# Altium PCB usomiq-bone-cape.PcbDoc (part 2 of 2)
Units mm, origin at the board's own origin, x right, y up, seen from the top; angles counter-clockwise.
Board outline 86.36 x 54.61 mm, 2 copper layers (Top Layer, Bottom Layer); 72 components, 131 nets, 473 pads, 192 vias.
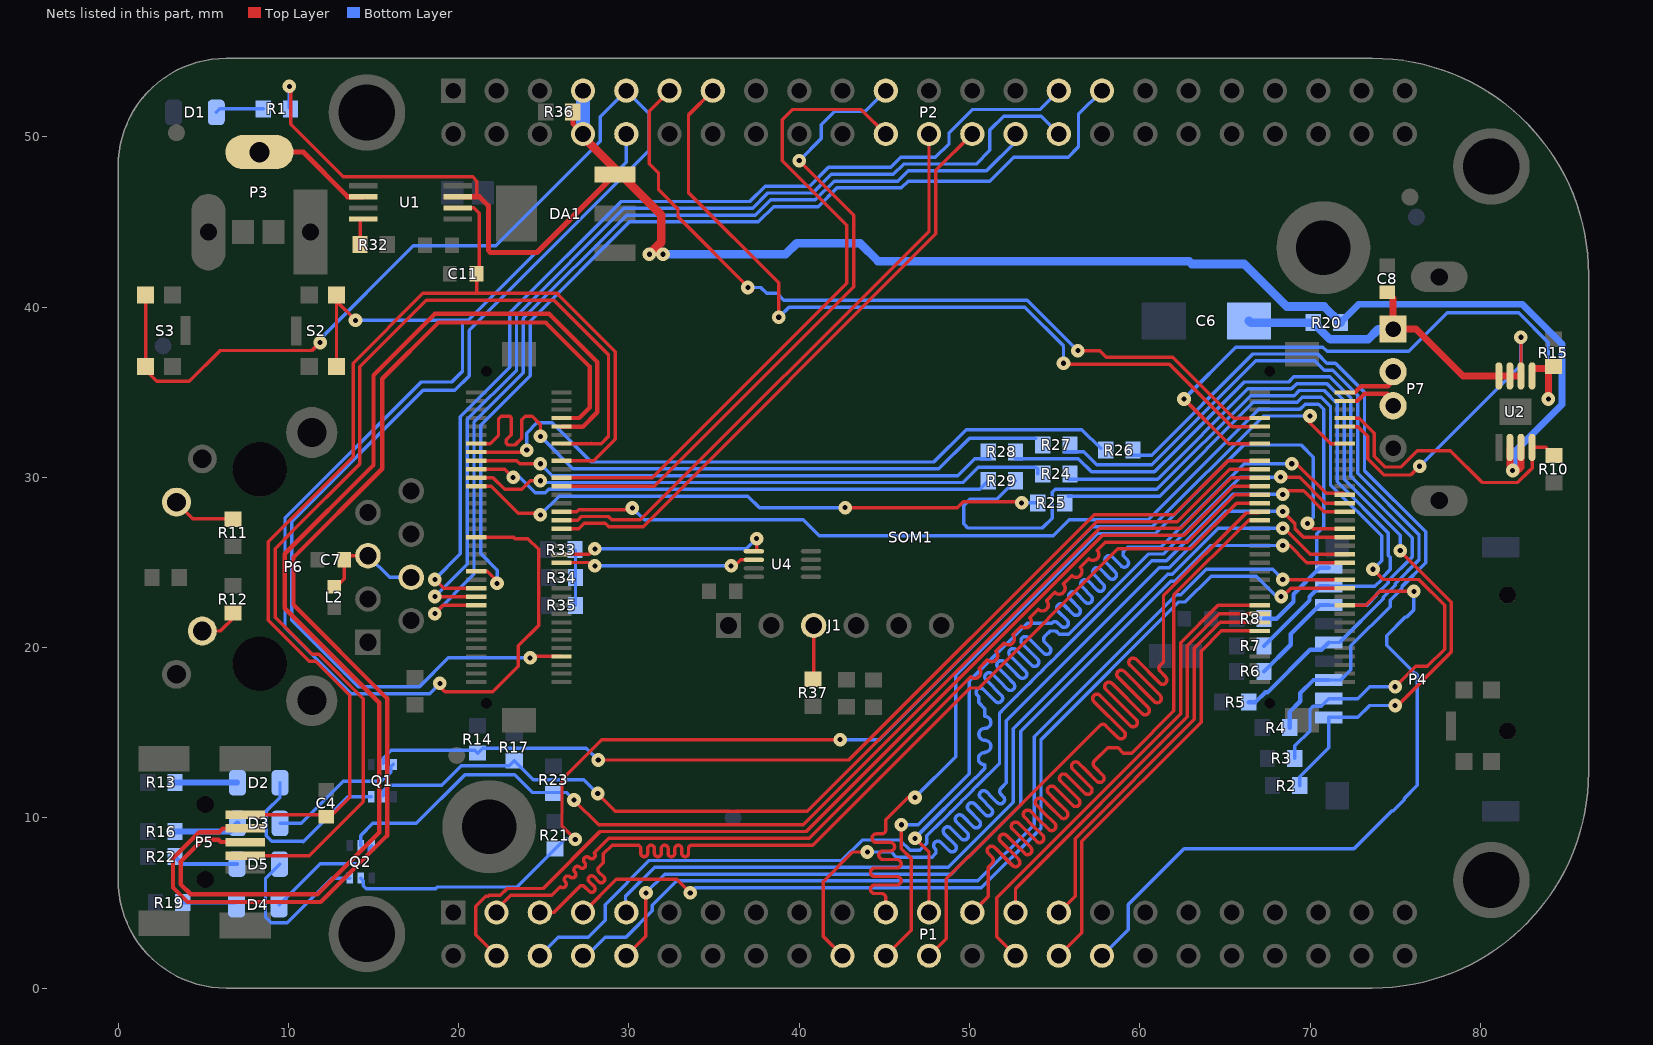
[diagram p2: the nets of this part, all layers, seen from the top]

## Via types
v1: diameter 0.8, hole 0.3, Top Layer to Bottom Layer, tented both sides, 187 vias
v2: diameter 0.4, hole 0.2, Top Layer to Bottom Layer, 5 vias

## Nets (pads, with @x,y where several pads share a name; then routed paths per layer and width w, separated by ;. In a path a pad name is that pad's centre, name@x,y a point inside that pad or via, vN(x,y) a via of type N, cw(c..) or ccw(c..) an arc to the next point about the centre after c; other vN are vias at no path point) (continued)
LCD_DATA15: P1.32 SOM1.B19 | length 40.8
  Top Layer w0.2: SOM1.B19@72.039,22.482 73.282,22.482 74.1,23.3 v1(76.1,23.3)
  Bottom Layer w0.2: P1.32@57.785,1.905 59.315,3.435 59.315,4.915 62.6,8.2 72.582,8.2 74.813,10.432 74.878,10.432 75.522,11.076 75.522,11.14 76.3,11.918 76.3,18.4 76.2,18.5 76.144,18.5 74.5,20.144 74.5,20.7 75.6,21.8 75.69,21.8 76.1,22.21 v1(76.1,23.3)
LCD_DE: P1.30 SOM1.B14 | length 25.3
  Top Layer w0.2: P1.30@55.245,1.905 56.6,3.26 56.6,8.617 63.6,15.617 63.6,19.79 64.792,20.982 SOM1.B14@67.039,20.982
LCD_HSYNC: P1.29 SOM1.B16 | length 23.3
  Top Layer w0.2: P1.29@55.245,4.445 56.2,5.4 56.2,8.783 63.2,15.783 63.2,19.956 64.726,21.482 SOM1.B16@67.039,21.482
LCD_PCLK: P1.28 SOM1.B20 | length 28.9
  Top Layer w0.2: P1.28@52.705,1.905 51.6,3.01 51.6,5.314 62.4,16.114 62.4,20.287 64.595,22.482 SOM1.B20@67.039,22.482
LCD_VSYNC: P1.27 SOM1.B18 | length 24.9
  Top Layer w0.2: P1.27@52.705,4.445 52.705,5.854 62.8,15.949 62.8,20.121 64.661,21.982 SOM1.B18@67.039,21.982
MMC0_CD: P4.9 R8.1 SOM1.A41 | length 63
  Top Layer w0.2: SOM1.A41@26.039,27.982 26.929,27.982 27.047,28.1 v1@29.864,28.1
  Bottom Layer w0.2: v1(30.2,28.2) 30.9,27.5 40.242,27.5 41.173,26.568 54.915,26.568 55.846,27.5 60.5,27.5 67,34 69.41,34 69.71,34.3 70.5,34.3 70.8,34 70.8,27.1 70.4,26.7 P4.9@70.4,24.9
  Bottom Layer w0.254: R8.1@67.3,21.7 68.028,21.7 69.027,22.699 69.027,23.139 70.588,24.7 P4.9@71.1,24.7
MMC0_CLKO: R27.2 SOM1.A58 | length 39.8
  Top Layer w0.2: SOM1.A58@21.039,31.982 21.866,31.982 22.339,32.455 22.339,33.421 22.5,33.582 23.018,33.582 23.1,33.5 23.1,32.5 22.8,32.2 22.8,32 22.9,31.9 23.31,31.9 23.7,32.29 23.7,33.382 23.9,33.582 24.31,33.582 24.807,33.085 v1(24.807,32.407)
  Bottom Layer w0.2: v1(24.807,32.407) 26.714,30.5 48.2,30.5 50,32.3 R27.2@53.9,32.3
MMC0_CMD: R26.2 SOM1.A56 | length 40.4
  Top Layer w0.2: SOM1.A56@21.039,31.482 23.882,31.482 v1(24,31.6) v1@24,31.8
  Bottom Layer w0.2: v1(24,31.6) 24,32.6 24.6,33.2 25.5,33.2 27.8,30.9 47.9,30.9 49.8,32.8 56.6,32.8 R26.2@57.7,31.7
MMC0_DAT0: R28.2 SOM1.A54 | length 30.9
  Top Layer w0.2: SOM1.A54@21.039,30.982 23.418,30.982 23.6,30.8 v1(24.8,30.8)
  Bottom Layer w0.2: v1(24.8,30.8) 25.5,30.1 49.3,30.1 50.3,31.1 51.1,31.1 R28.2@51.2,31.1
MMC0_DAT1: R29.2 SOM1.A52 | length 30.9
  Top Layer w0.2: SOM1.A52@21.039,30.482 22.718,30.482 v1(23.2,30)
  Bottom Layer w0.2: v1(23.2,30) 23.6,30 24.5,29.1 25.09,29.1 25.29,29.3 50.6,29.3 R29.2@51.1,29.8
MMC0_DAT2: R24.2 SOM1.A50 | length 34.2
  Top Layer w0.2: SOM1.A50@21.039,29.982 22.018,29.982 22.7,29.3 23.7,29.3 24.2,29.8 v1(24.8,29.8)
  Bottom Layer w0.2: v1(24.8,29.8) 24.9,29.7 49.626,29.7 50.526,30.6 53.9,30.6 54,30.5 R24.2@54,30.2
MMC0_DAT3: R25.2 SOM1.A48 | length 34.6
  Top Layer w0.2: SOM1.A48@21.039,29.482 21.918,29.482 23.5,27.9 24.7,27.9 v1(24.8,27.8) ; v1(42.697,28.219) 49.276,28.219 49.632,28.575 52.984,28.575 v1(53.061,28.499)
  Bottom Layer w0.2: v1(24.8,27.8) 25.9,28.9 36.988,28.9 37.668,28.219 v1(42.697,28.219) ; v1(53.061,28.499) 53.999,28.499 R25.2@54,28.5
MMC1_CLK: P1.21 SOM1.B37 | length 58.1
  Top Layer w0.2: P1.21@45.085,4.445 45.085,5.309 ccw(c44.835,5.309) 44.835,5.559 44.435,5.559 cw(c44.435,5.809) 44.185,5.809 cw(c44.435,5.809) 44.435,6.059 45.735,6.059 ccw(c45.735,6.309) 45.985,6.309 ccw(c45.735,6.309) 45.735,6.559 44.435,6.559 cw(c44.435,6.809) 44.185,6.809 cw(c44.435,6.809) 44.435,7.059 45.735,7.059 ccw(c45.735,7.309) 45.985,7.309 ccw(c45.735,7.309) 45.735,7.559 44.93,7.559 cw(c44.93,7.809) 44.68,7.809 cw(c44.93,7.809) 44.93,8.059 45.35,8.059 ccw(c45.35,8.309) 45.6,8.309 ccw(c45.35,8.309) 45.35,8.559 44.525,8.559 cw(c44.525,8.809) 44.275,8.809 cw(c44.525,8.809) 44.525,9.059 44.835,9.059 ccw(c44.835,9.309) 45.085,9.309 45.085,9.885 46.4,11.2 v1(46.8,11.2) ; v1(69.85,27.3) 70.168,26.982 SOM1.B37@72.039,26.982
  Bottom Layer w0.2: v1(46.8,11.2) 49.194,13.594 49.194,18.383 57.51,26.7 60.909,26.7 66.109,31.9 69.471,31.9 70.2,31.171 70.2,27.65 v1(69.85,27.3)
MMC1_CMD: P1.20 SOM1.B35 | length 58.9
  Top Layer w0.2: P1.20@42.545,1.905 41.415,3.035 41.415,6.261 43.154,8 v1(44,8) ; v1(68.4,28) 68.61,28 68.61,27.79 69.116,27.284 69.116,26.984 69.618,26.482 SOM1.B35@72.039,26.482
  Bottom Layer w0.2: v1(44,8) 45.4,8 45.7,7.7 47.807,7.7 47.961,7.855 ccw(c47.785,8.032) 47.961,8.208 ; 47.961,8.209 cw(c48.138,8.386) 47.961,8.562 cw(c48.138,8.386) 48.315,8.562 48.801,8.076 ccw(c48.978,8.253) 49.155,8.076 ccw(c48.978,8.253) 49.155,8.429 48.534,9.05 cw(c48.711,9.226) 48.534,9.403 cw(c48.711,9.226) 48.888,9.403 49.514,8.777 ccw(c49.691,8.954) 49.868,8.777 ccw(c49.691,8.954) 49.868,9.131 49.242,9.757 cw(c49.418,9.934) 49.242,10.11 cw(c49.418,9.934) 49.595,10.11 50.221,9.484 ccw(c50.398,9.661) 50.575,9.484 ccw(c50.398,9.661) 50.575,9.838 49.949,10.464 cw(c50.125,10.641) 49.949,10.817 cw(c50.125,10.641) 50.302,10.817 50.928,10.191 ccw(c51.105,10.368) 51.282,10.191 ccw(c51.105,10.368) 51.282,10.545 50.656,11.171 cw(c50.833,11.348) 50.656,11.524 cw(c50.833,11.348) 51.009,11.524 51.32,11.214 51.635,10.899 ccw(c51.812,11.075) 51.989,10.899 ccw(c51.812,11.075) 51.989,11.252 51.851,11.39 cw(c52.027,11.567) 51.851,11.744 52.165,12.059 52.165,15.711 61.154,24.7 61.737,24.7 65.037,28 v1(68.4,28)
MMC1_DAT0: P1.25 SOM1.B40 | length 60
  Top Layer w0.2: P1.25@50.165,4.445 51.105,5.385 51.105,7.112 51.332,7.34 ccw(c51.156,7.516) 51.332,7.693 51.115,7.911 cw(c51.291,8.088) 51.115,8.265 cw(c51.291,8.088) 51.468,8.265 52.527,7.205 ccw(c52.704,7.382) 52.881,7.205 ccw(c52.704,7.382) 52.881,7.559 51.822,8.618 cw(c51.999,8.795) 51.822,8.972 cw(c51.999,8.795) 52.175,8.972 53.235,7.912 ccw(c53.411,8.089) 53.588,7.912 ccw(c53.411,8.089) 53.588,8.266 52.529,9.325 cw(c52.706,9.502) 52.529,9.679 cw(c52.706,9.502) 52.882,9.679 53.942,8.619 ccw(c54.118,8.796) 54.295,8.619 ccw(c54.118,8.796) 54.295,8.973 53.631,9.638 53.236,10.032 cw(c53.413,10.209) 53.236,10.386 cw(c53.413,10.209) 53.589,10.386 53.984,9.991 54.649,9.327 ccw(c54.826,9.503) 55.002,9.327 ccw(c54.826,9.503) 55.002,9.68 54.338,10.345 53.943,10.739 cw(c54.12,10.916) 53.943,11.093 cw(c54.12,10.916) 54.297,11.093 54.691,10.698 55.356,10.034 ccw(c55.533,10.21) 55.709,10.034 ccw(c55.533,10.21) 55.709,10.387 55.045,11.052 54.65,11.447 cw(c54.827,11.623) 54.65,11.8 cw(c54.827,11.623) 55.004,11.8 55.398,11.405 56.063,10.741 ccw(c56.24,10.918) 56.417,10.741 ccw(c56.24,10.918) 56.417,11.094 55.752,11.759 55.357,12.154 cw(c55.534,12.33) 55.357,12.507 cw(c55.534,12.33) 55.711,12.507 56.105,12.113 56.77,11.448 ccw(c56.947,11.625) 57.124,11.448 ccw(c56.947,11.625) 57.124,11.801 56.459,12.466 56.064,12.861 cw(c56.241,13.038) 56.064,13.214 cw(c56.241,13.038) 56.418,13.214 56.812,12.82 57.477,12.155 ccw(c57.654,12.332) 57.831,12.155 ccw(c57.654,12.332) 57.831,12.509 57.343,12.996 cw(c57.52,13.173) 57.343,13.35 58.115,14.122 58.725,14.122 59.039,13.808 59.528,13.808 62,16.28 62,23.092 66.39,27.482 SOM1.B40@67.039,27.482
MMC1_DAT1: P1.24 SOM1.B42 | length 58.3
  Top Layer w0.2: P1.24@47.625,1.905 48.635,2.915 48.635,6.425 49.91,7.7 49.94,7.7 57.662,15.422 cw(c57.839,15.245) 58.016,15.422 58.723,14.715 ccw(c58.9,14.892) 59.077,14.715 ccw(c58.9,14.892) 59.077,15.069 57.309,16.836 cw(c57.486,17.013) 57.309,17.19 cw(c57.486,17.013) 57.662,17.19 59.43,15.422 ccw(c59.607,15.599) 59.784,15.422 ccw(c59.607,15.599) 59.784,15.776 58.016,17.544 cw(c58.193,17.72) 58.016,17.897 cw(c58.193,17.72) 58.37,17.897 60.137,16.129 ccw(c60.314,16.306) 60.491,16.129 ccw(c60.314,16.306) 60.491,16.483 58.723,18.251 cw(c58.9,18.427) 58.723,18.604 cw(c58.9,18.427) 59.077,18.604 60.844,16.836 ccw(c61.021,17.013) 61.198,16.836 ccw(c61.021,17.013) 61.198,17.19 59.43,18.958 cw(c59.607,19.135) 59.43,19.311 cw(c59.607,19.135) 59.784,19.311 61.173,17.922 ccw(c61.35,18.099) 61.527,17.922 ccw(c61.35,18.099) 61.527,18.275 61.198,18.604 cw(c61.375,18.781) 61.198,18.958 61.392,19.152 61.392,23.05 66.249,27.907 66.964,27.907 SOM1.B42@67.039,27.982
MMC1_DAT2: P1.5 SOM1.B44 | length 59.1
  Top Layer w0.2: P1.5@24.765,4.445 25.578,4.445 27.104,5.971 cw(c27.245,5.83) 27.386,5.971 27.67,5.688 ccw(c27.811,5.83) 27.952,5.688 ccw(c27.811,5.83) 27.952,5.971 27.67,6.254 ; 27.669,6.254 cw(c27.811,6.395) 27.67,6.537 cw(c27.811,6.395) 27.952,6.537 28.235,6.254 ; 28.235,6.254 ccw(c28.377,6.395) 28.518,6.254 ccw(c28.377,6.395) 28.518,6.537 28.235,6.82 cw(c28.377,6.961) 28.235,7.102 28.5,7.367 28.5,7.89 29.01,8.4 30.499,8.4 cw(c30.499,8.2) 30.699,8.2 30.699,7.922 ccw(c30.899,7.922) 30.899,7.722 ccw(c30.899,7.922) 31.099,7.922 31.099,8.2 cw(c31.299,8.2) 31.299,8.4 cw(c31.299,8.2) 31.499,8.2 31.499,7.922 ccw(c31.699,7.922) 31.699,7.722 ccw(c31.699,7.922) 31.899,7.922 31.899,8.2 cw(c32.099,8.2) 32.099,8.4 cw(c32.099,8.2) 32.299,8.2 32.299,7.922 ccw(c32.499,7.922) 32.499,7.722 ccw(c32.499,7.922) 32.699,7.922 32.699,8.2 cw(c32.899,8.2) 32.899,8.4 cw(c32.899,8.2) 33.099,8.2 33.099,7.922 ccw(c33.299,7.922) 33.299,7.722 ccw(c33.299,7.922) 33.499,7.922 33.499,8.2 cw(c33.699,8.2) 33.699,8.4 40.792,8.4 50.013,17.62 50.013,17.628 50.521,17.628 50.533,17.615 58.718,25.8 63,25.8 65.682,28.482 SOM1.B44@67.039,28.482
MMC1_DAT3: P1.6 SOM1.B41 | length 62.1
  Top Layer w0.2: v1@68.4,29.2 68.401,29.201 69.618,29.201 70.838,27.982 SOM1.B41@72.039,27.982
  Bottom Layer w0.2: P1.6@24.765,1.905 25.86,3 27.6,3 28.6,4 28.6,4.9 31.2,7.5 42.5,7.5 43.7,8.7 45.91,8.7 46.51,8.1 47.09,8.1 47.5,8.51 47.5,8.952 48.386,9.839 48.404,9.839 48.806,10.24 48.806,10.258 49.093,10.546 49.111,10.546 49.513,10.948 49.513,10.966 49.801,11.253 49.819,11.253 50.22,11.655 50.22,11.673 50.508,11.96 50.526,11.96 51.765,13.2 51.765,16.159 52.018,16.412 52.025,16.412 52.169,16.556 ; 52.165,16.559 52.169,16.556 ; 52.872,17.266 52.876,17.263 ; 53.579,17.973 53.583,17.97 ; 54.287,18.68 54.29,18.677 ; 54.994,19.387 54.997,19.384 ; v1(68.4,29) 65.472,29 61.572,25.1 60.706,25.1 55.141,19.535 55.141,19.528 54.997,19.384 ; 52.169,16.556 52.312,16.699 52.312,16.706 52.725,17.119 52.732,17.119 52.876,17.263 ; 52.876,17.263 53.019,17.406 53.019,17.414 53.432,17.826 53.439,17.826 53.583,17.97 ; 53.583,17.97 53.727,18.113 53.727,18.121 54.139,18.533 54.146,18.533 54.29,18.677 ; 54.29,18.677 54.434,18.821 54.434,18.828 54.846,19.24 54.853,19.24 54.997,19.384
MMC1_DAT4: P1.23 SOM1.B43 | length 58.5
  Top Layer w0.2: v1(46.8,8.8) 47.625,7.975 P1.23@47.625,4.445 ; v1@68.4,30 69.385,30 70.903,28.482 SOM1.B43@72.039,28.482
  Bottom Layer w0.2: v1(46.8,8.8) 46.8,8.818 50.342,12.36 50.36,12.36 50.902,12.902 50.902,13.129 ; 50.876,13.129 cw(c50.876,13.479) 50.876,13.829 ; 50.902,13.857 ccw(c50.902,14.207) 50.902,14.557 cw(c50.902,14.907) 50.902,15.257 ccw(c50.902,15.607) 50.902,15.957 50.902,16.408 50.533,16.777 50.533,17.13 50.467,17.197 cw(c50.644,17.374) 50.467,17.55 cw(c50.644,17.374) 50.82,17.55 51.523,16.847 ccw(c51.7,17.024) 51.877,16.847 ccw(c51.7,17.024) 51.877,17.201 50.975,18.103 cw(c51.152,18.279) 50.975,18.456 cw(c51.152,18.279) 51.329,18.456 51.771,18.014 52.23,17.555 ccw(c52.407,17.731) 52.584,17.555 ccw(c52.407,17.731) 52.584,17.908 52.124,18.368 51.682,18.81 cw(c51.859,18.987) 51.682,19.163 cw(c51.859,18.987) 52.036,19.163 52.478,18.721 52.937,18.262 ccw(c53.114,18.438) 53.291,18.262 ccw(c53.114,18.438) 53.291,18.615 52.831,19.075 52.389,19.517 cw(c52.566,19.694) 52.389,19.87 cw(c52.566,19.694) 52.743,19.87 53.185,19.428 53.645,18.969 ccw(c53.821,19.146) 53.998,18.969 ccw(c53.821,19.146) 53.998,19.322 53.538,19.782 53.096,20.224 cw(c53.273,20.401) 53.096,20.578 cw(c53.273,20.401) 53.45,20.578 53.892,20.135 54.352,19.676 ccw(c54.528,19.853) 54.705,19.676 ccw(c54.528,19.853) 54.705,20.029 54.422,20.312 cw(c54.599,20.489) 54.422,20.666 54.733,20.976 55.081,20.976 55.283,20.774 55.761,20.774 55.783,20.796 55.836,20.796 60.54,25.5 61.406,25.5 65.906,30 v1@68.275,30
  other v1: 68.275,30.025
MMC1_DAT5: P1.22 SOM1.B45 | length 58.7
  Top Layer w0.2: P1.22@45.085,1.905 46.584,3.404 46.584,7.616 46,8.2 v1(46,9.6) ; v1@69.261,30.861 69.261,30.8 69.261,30.752 70.955,29.057 71.964,29.057 SOM1.B45@72.039,28.982
  Bottom Layer w0.2: v1(46,9.6) 47,9.6 49.994,12.594 49.994,18.04 53.396,21.443 54.844,21.443 cw(c55.021,21.266) 55.198,21.443 55.381,21.26 ccw(c55.558,21.437) 55.734,21.26 ccw(c55.558,21.437) 55.734,21.613 55.199,22.149 cw(c55.376,22.326) 55.199,22.502 cw(c55.376,22.326) 55.553,22.502 56.088,21.967 ccw(c56.265,22.144) 56.442,21.967 ccw(c56.265,22.144) 56.442,22.321 55.906,22.856 cw(c56.083,23.033) 55.906,23.21 cw(c56.083,23.033) 56.26,23.21 56.795,22.674 ccw(c56.972,22.851) 57.149,22.674 ccw(c56.972,22.851) 57.149,23.028 56.613,23.563 cw(c56.79,23.74) 56.613,23.917 cw(c56.79,23.74) 56.967,23.917 57.502,23.381 ccw(c57.679,23.558) 57.856,23.381 ccw(c57.679,23.558) 57.856,23.735 57.32,24.27 cw(c57.497,24.447) 57.32,24.624 cw(c57.497,24.447) 57.674,24.624 58.209,24.088 ccw(c58.386,24.265) 58.563,24.088 ccw(c58.386,24.265) 58.563,24.442 58.027,24.977 cw(c58.204,25.154) 58.027,25.331 cw(c58.204,25.154) 58.381,25.331 58.916,24.795 ccw(c59.093,24.972) 59.27,24.795 ccw(c59.093,24.972) 59.27,25.149 59.087,25.332 cw(c59.264,25.509) 59.087,25.686 59.301,25.9 61.24,25.9 66.14,30.8 v1(68.925,30.8) v1@69,30.8
MMC1_DAT6: P1.3 SOM1.B46 | length 60
  Top Layer w0.2: P1.3@22,4.4 22.135,4.535 23.055,5.455 25.47,5.455 25.979,5.964 ccw(c26.121,6.106) 26.262,6.247 cw(c26.404,6.388) 26.545,6.53 ccw(c26.686,6.671) 26.828,6.813 cw(c26.969,6.954) 27.111,7.096 ccw(c27.252,7.237) 27.394,7.378 cw(c27.535,7.52) 27.676,7.661 ccw(c27.818,7.803) 27.959,7.944 28.815,8.8 40.579,8.8 50.07,18.291 ccw(c50.312,18.544) 50.565,18.786 51.06,19.281 ccw(c51.307,19.529) 51.555,19.776 52.05,20.271 ccw(c52.297,20.519) 52.545,20.766 53.04,21.261 ccw(c53.287,21.509) 53.535,21.756 54.03,22.251 ccw(c54.277,22.499) 54.525,22.746 55.02,23.241 ccw(c55.267,23.488) 55.515,23.736 56.01,24.231 ccw(c56.257,24.478) 56.505,24.726 57,25.221 ccw(c57.247,25.468) 57.495,25.716 57.979,26.2 62.8,26.2 65.582,28.982 SOM1.B46@67.039,28.982
MMC1_DAT7: P1.4 SOM1.B48 | length 59.7
  Top Layer w0.2: P1.4@22.225,1.905 21,3.13 21,4.8 21.6,5.4 21.752,5.4 21.807,5.455 22.455,5.455 22.855,5.855 24.956,5.855 28.301,9.2 40.413,9.2 57.813,26.6 62.6,26.6 65.482,29.482 SOM1.B48@67.039,29.482
NetC7_1: C7.1 L2.2 P6.4 P6.5 | length 6.3
  Top Layer w0.2: L2.2@12.862,23.612 13.284,24.034 C7.1@13.284,25.171 13.508,25.395 P6.5@14.675,25.395
  Bottom Layer w0.2: P6.5@14.675,25.395 15.945,24.125 P6.4@17.215,24.125
NetD1_1: D1.1 R1.1 | length 2.8
  Bottom Layer w0.2: D1.1@5.766,51.435 5.969,51.638 R1.1@8.522,51.638
NetD2_1: D2.1 R13.1 | length 3.6
  Bottom Layer w0.35: R13.1@3.34,12.09 D2.1@6.985,12.09
NetD2_2: D2.2 Q1.6 | length 10.8
  Bottom Layer w0.2: D2.2@9.51,12.065 9.51,11.205 8.71,10.405 8.71,8.95 9.033,8.627 10.854,8.627 10.871,8.611 13.503,11.242 Q1.6@14.869,11.242
NetD3_1: D3.1 R16.1 | length 3.9
  Bottom Layer w0.35: R16.1@3.34,9.195 6.528,9.195 D3.1@7.01,9.677
NetD3_2: D3.2 Q1.3 | length 8.3
  Bottom Layer w0.2: D3.2@9.51,9.677 10.77,9.677 13.233,12.141 15.468,12.141 16.019,12.693 16.019,12.992 Q1.3@16.169,13.142
NetD4_1: D4.1 R19.1 | length 3
  Bottom Layer w0.254: R19.1@3.797,5.029 D4.1@6.833,5.029
NetD4_2: D4.2 Q2.6 | length 7.1
  Bottom Layer w0.2: D4.2@9.46,4.902 11.873,7.315 14.147,7.315 14.749,7.918 14.749,8.217 Q2.6@14.899,8.367
NetD5_1: D5.1 R22.1 | length 3.8
  Bottom Layer w0.254: R22.1@3.34,7.722 3.772,7.29 D5.1@6.985,7.29
NetD5_2: D5.2 Q2.3 | length 9.6
  Bottom Layer w0.2: D5.2@9.485,7.29 8.66,6.464 8.66,4.174 8.982,3.852 9.937,3.852 12.552,6.467 Q2.3@13.599,6.467
NetJ1_3: J1.3 R37.1 | length 3.1
  Top Layer w0.2: R37.1@40.85,18.18 J1.3@40.85,21.3
NetP6_10: P6.10 R12.2 | length 2.3
  Top Layer w0.2: P6.10@4.945,20.975 6,20.975 R12.2@6.875,21.85
NetP6_11: P6.11 R11.2 | length 3.7
  Top Layer w0.2: P6.11@3.425,28.545 4.395,27.575 R11.2@6.756,27.575
NetR32_1: R32.1 U1.4 | length 1.3
  Top Layer w0.2: R32.1@14.211,43.663 14.211,44.993
NetR33_2: R33.2 R34.2 R35.2 | length 3.3
  Bottom Layer w0.2: R35.2@26.86,22.479 R34.2@26.86,24.105 R33.2@26.86,25.73
PWR_BUT: P2.9 S3.2 S3.4 SOM1.A7 | length 100.4
  Top Layer w0.2: S3.2@1.626,40.488 1.626,36.288 2.277,35.636 4.191,35.636 6.005,37.45 11.389,37.45 v1(11.862,37.922) ; v1(24.2,19.4) 24.282,19.482 SOM1.A7@26.039,19.482
  Bottom Layer w0.2: v1(11.862,37.922) 11.862,38.125 17.336,43.599 22.175,43.599 28.315,49.739 28.315,51.175 P2.9@29.845,52.705 31.19,51.36 ; v1(24.2,19.4) 19.4,19.4 17.7,17.7 14.1,17.7 10.2,21.6 10.2,27.4 17.906,35.106 19.78,35.106 20.626,35.952 20.626,38.627 31.2,49.2 31.2,51.36
SD_CLK: P4.5 R5.1 R27.1 | length 45.6
  Bottom Layer w0.2: R27.1@55.6,31.5 55.9,31.5 56.7,31.5 57.467,30.733 60.699,30.733 66.81,36.845 70.284,36.845 70.828,36.3 71.328,36.3 72.8,34.828 72.8,30.228 76.4,26.628 76.4,25.156 75,23.756 75,23.655 74.944,23.6 74.3,22.956 74.3,22.868 71.731,20.3 P4.5@71.1,20.3
  Bottom Layer w0.254: R5.1@66.4,16.8 66.803,16.8 67.374,17.372 67.5,17.372 70.005,19.877 70.677,19.877 P4.5@71.1,20.3
SD_CMD: P4.3 R4.1 R26.1 | length 42.5
  Bottom Layer w0.2: R26.1@59.5,31.3 59.6,31.3 60.7,31.3 66.644,37.245 70.45,37.245 70.994,36.7 71.494,36.7 73.2,34.994 73.2,30.4 76.8,26.8 76.8,24.99 75.4,23.59 75.4,23.49 75.11,23.2 74.7,22.79 74.7,22.4 72.4,20.1 72.4,18.7 71.8,18.1 P4.3@71.1,18.1
  Bottom Layer w0.254: R4.1@68.8,15.3 68.8,16.222 69.427,16.849 69.427,17.327 70.2,18.1 P4.3@71.1,18.1
SD_D0: P4.7 R6.1 R28.1 | length 45.6
  Bottom Layer w0.2: R28.1@52.7,31.1 56.4,31.1 57.167,30.333 60.865,30.333 66.131,35.6 68.747,35.6 69.047,35.9 71.163,35.9 72.4,34.663 72.4,30.063 76,26.463 76,25.321 74.6,23.921 74.6,23.821 73.9,23.121 73.9,23.034 73.366,22.5 P4.7@71.1,22.5
  Bottom Layer w0.254: R6.1@67.3,18.6 68.873,20.173 68.873,20.801 70.572,22.5 P4.7@71.1,22.5
SD_D1: P4.8 R7.1 R29.1 | length 51.8
  Bottom Layer w0.2: R29.1@52.7,29.8 51.602,28.702 50.013,28.702 49.657,28.346 49.657,27.28 49.911,27.026 54.28,27.026 54.85,27.596 54.85,29.124 55.026,29.3 61.01,29.3 66.51,34.8 69.079,34.8 69.379,35.1 70.831,35.1 71.6,34.331 71.6,29.731 74.6,26.731 74.6,25.41 74.7,25.31 74.7,24.587 74.2,24.087 74.2,23.987 73.813,23.6 P4.8@71.1,23.6
  Bottom Layer w0.254: R7.1@67.3,20.1 69.973,22.773 69.973,22.985 70.588,23.6 P4.8@71.1,23.6
SD_D2: P4.1 R2.1 R24.1 | length 49.8
  Top Layer w0.2: v1(75,16.6) 75.156,16.6 78.3,19.744 78.3,22.656 75.3,25.655 v1(75.3,25.7)
  Bottom Layer w0.2: R24.1@55.8,29.9 55.9,29.9 61.044,29.9 66.344,35.2 68.913,35.2 69.213,35.5 70.997,35.5 72,34.497 72,29.897 75.3,26.597 v1(75.3,25.7) ; R2.1@69.4,11.9 69.4,12.426 71.1,14.126 P4.1@71.1,15.9 72.8,15.9 73.5,16.6 v1(75,16.6)
SD_D3: P4.2 R3.1 R25.1 | length 49.3
  Top Layer w0.2: v1(73.7,24.6) 74.3,24 76.39,24 77.9,22.49 77.9,19.91 76.89,18.9 76.2,18.9 v1(75,17.7)
  Bottom Layer w0.2: R25.1@55.8,28.9 61.175,28.9 66.675,34.4 69.244,34.4 69.544,34.7 70.666,34.7 71.2,34.166 71.2,29.566 74.2,26.566 74.2,25.1 v1(73.7,24.6) ; R3.1@69.1,13.5 69.1,14.226 70,15.126 70,16.374 70.176,16.55 70.65,16.55 P4.2@71.1,17 72.8,17 73.5,17.7 v1(75,17.7)
SPI1_CS0: P2.28 SOM1.A20 | length 55.3
  Top Layer w0.2: v1(18.6,22) 19.082,22.482 SOM1.A20@21.039,22.482
  Bottom Layer w0.2: v1(18.6,22) 20.9,24.3 20.9,33.235 23.8,36.135 23.8,39.331 29.869,45.4 37.43,45.4 38.33,46.3 40.953,46.3 42.053,47.4 45.8,47.4 46.4,48 51,48 P2.28@52.705,49.705
SPI1_D0: P2.29 SOM1.A24 | length 58.2
  Top Layer w0.2: v1(18.6,24) 19.118,23.482 SOM1.A24@21.039,23.482
  Bottom Layer w0.2: v1(18.6,24) 20.1,25.5 20.1,33.566 23,36.466 23,39.663 29.537,46.2 37.099,46.2 37.999,47.1 40.621,47.1 41.721,48.2 45.366,48.2 45.966,48.8 48,48.8 48.8,49.6 48.8,50.228 50.172,51.6 54.14,51.6 P2.29@55.245,52.705
SPI1_D1: P2.30 SOM1.A22 | length 58.8
  Top Layer w0.2: v1(18.6,23) 18.618,22.982 SOM1.A22@21.039,22.982
  Bottom Layer w0.2: v1(18.6,23) 20.5,24.9 20.5,33.4 23.4,36.3 23.4,39.497 29.703,45.8 37.264,45.8 38.164,46.7 40.787,46.7 41.887,47.8 45.531,47.8 46.131,48.4 50.4,48.4 51.2,49.2 51.2,50.4 52,51.2 54.21,51.2 P2.30@55.245,50.165
SPI1_SCLK: P2.31 SOM1.A28 | length 58.6
  Top Layer w0.2: SOM1.A28@21.387,24.486 21.685,24.486 22.25,23.92 v1(22.25,23.774)
  Bottom Layer w0.2: v1(22.25,23.774) 22.276,23.8 22.276,24.551 21.3,25.527 21.3,33.069 24.2,35.969 24.2,39.166 30.034,45 37.596,45 38.496,45.9 41.118,45.9 42.218,47 46,47 46.4,47.4 51.2,47.4 52.6,48.8 55.8,48.8 56.4,49.4 56.4,51.32 P2.31@57.785,52.705
SYS_5V: DA1.3 P2.7 P2.8 R1.2 R20.2 R36.2 U1.7 U2.2 U2.3 | length 112.3
  Top Layer w0.2: v1(10.058,52.959) 10.135,52.883 10.135,50.749 13.233,47.65 20.821,47.65 21.07,47.401 21.07,46.621 21.214,46.477
  Top Layer w0.3: U1.7@19.945,46.477 21.214,46.477 21.742,45.949 21.742,43.332 21.869,43.205 24.603,43.205 DA1.3@29.189,47.791 ; R36.2@26.708,51.46 26.708,50.762 P2.8@27.305,50.165
  Top Layer w0.4: U2.2@81.739,31.757 81.739,30.661 82.1,30.3 82.389,30.589 U2.3@82.389,31.757
  Top Layer w0.508: P2.8@27.305,49.995 31.9,45.4 31.9,43.8 v1(31.2,43.1)
  Bottom Layer w0.2: R1.2@10.058,51.702 v1(10.058,52.959)
  Bottom Layer w0.4: R20.2@71.789,39.082 72.877,40.17 82.457,40.17 84.8,37.827 84.8,34.269 82.1,31.569 v1@82.1,30.3
  Bottom Layer w0.508: v1(32,43.1) 39.2,43.1 39.854,43.754 43.57,43.754 44.624,42.7 62.896,42.7 63.068,42.528 66.133,42.528 68.625,40.036 70.827,40.036 71.781,39.082 R20.2@71.789,39.082
  Bottom Layer w0.8: P2.8@27.305,50.165 P2.7@27.305,52.705
  other v1: 81.9,30.4
SYS_RESETN: P2.10 S2.2 S2.4 SOM1.A36 | length 78
  Top Layer w0.2: S2.2@12.827,36.5 12.827,40.335 v1(13.945,39.218) ; v1(18.9,17.9) 18.9,17.7 19.2,17.4 22,17.4 23.5,18.9 23.5,20.1 24.7,21.3 24.7,25.77 24.07,26.4 23.31,26.4 23.228,26.482 SOM1.A36@21.039,26.482
  Bottom Layer w0.2: v1(13.945,39.218) 13.954,39.227 20.227,39.227 ; v1(18.9,17.9) 18.3,17.3 13.7,17.3 9.8,21.2 9.8,27.6 17.8,35.6 19.59,35.6 20.227,36.237 20.227,39.227 ; P2.10@29.845,50.165 29.845,48.514 20.558,39.227 20.227,39.227
TIMER4: P1.7 SOM1.B23 | length 58
  Top Layer w0.2: P1.7@27.305,4.445 29.26,6.4 32.8,6.4 v1(33.6,5.6) ; v1@68.239,22.839 68.35,22.95 68.882,23.482 SOM1.B23@72.039,23.482
  Bottom Layer w0.2: v1(33.6,5.6) 33.9,5.9 50.7,5.9 54.2,9.4 54.2,14.593 62.289,22.682 62.682,22.682 64.2,24.2 66.839,24.2 68.169,22.87 68.239,22.8 68.3,22.861 v1(68.3,23) v1@68.3,23.293
TIMER5: P1.9 SOM1.B31 | length 55.3
  Top Layer w0.2: v1@68.575,26.925 70.018,25.482 SOM1.B31@72.039,25.482
  Bottom Layer w0.2: P1.9@29.8,4.2 29.8,4.445 29.8,5.39 31.51,7.1 48.756,7.1 49.1,7.444 49.1,7.456 49.744,8.1 49.756,8.1 52.576,10.92 52.576,15.232 61.644,24.3 61.903,24.3 64.603,27 v1(68.4,27)
TIMER6: P1.10 SOM1.B29 | length 56.6
  Top Layer w0.2: P1.10@29.845,1.905 31,3.06 v1(31,5.6) ; v1(68.4,26) 68.8,26 69.818,24.982 SOM1.B29@72.039,24.982
  Bottom Layer w0.2: v1(31,5.6) 32.1,6.7 48.922,6.7 49.5,7.278 49.5,7.29 49.91,7.7 49.922,7.7 53,10.778 53,15.09 61.81,23.9 62.069,23.9 64.169,26 v1(68.4,26)
TIMER7: P1.8 SOM1.B25 | length 57.3
  Top Layer w0.2: v1(68.4,24) 68.418,23.982 SOM1.B25@72.039,23.982
  Bottom Layer w0.2: P1.8@27.6,2 28.6,3 29.828,3 31.375,4.547 31.375,4.863 32.812,6.3 50.49,6.3 53.8,9.61 53.8,14.759 62.141,23.1 62.4,23.1 63.9,24.6 67.8,24.6 v1(68.4,24)
UART0_RX: SOM1.A29 U4.6 | length 11.6
  Top Layer w0.2: SOM1.A29@26.2,25 27.8,25 v1(28,24.8) ; v1(36,24.8) 36.2,24.8 36.557,25.157 U4.6@37.339,25.157
  Bottom Layer w0.2: v1@28.194,24.606 v1(28,24.8) v1(36,24.8)
UART0_TX: SOM1.A31 U4.5 | length 12.5
  Top Layer w0.2: SOM1.A31@26.039,25.482 27.682,25.482 v1(28,25.8) ; U4.5@37.5,25.7 v1(37.5,26.4)
  Bottom Layer w0.2: v1(28,25.8) 36.9,25.8 v1(37.5,26.4)
UART1_RXD: P2.26 SOM1.A37 | length 36.1
  Top Layer w0.2: SOM1.A37@26.039,26.982 27.061,26.982 27.379,27.3 28.621,27.3 28.821,27.1 30.831,27.1 48.025,44.294 48.025,48.025 P2.26@50.165,50.165
UART1_TXD: P2.24 SOM1.A39 | length 34.5
  Top Layer w0.2: SOM1.A39@26.039,27.482 26.995,27.482 27.213,27.7 28.787,27.7 28.987,27.5 30.666,27.5 47.625,44.459 P2.24@47.625,50.165
UART2_RXD: P2.22 SOM1.A49 | length 39.6
  Top Layer w0.2: SOM1.A49@26.039,29.982 31.382,29.982 42.8,41.4 42.8,44.8 39,48.6 39,49.742 38.995,49.747 38.995,50.995 39.6,51.6 43.65,51.6 P2.22@45.085,50.165
UART2_TXD: P2.21 SOM1.A47 | length 37.6
  Top Layer w0.2: SOM1.A47@26.039,29.482 31.482,29.482 43.2,41.2 43.2,45.4 40.3,48.3
  Bottom Layer w0.2: v1(40,48.6) 41.3,49.9 41.3,50.7 42.1,51.5 43.88,51.5 P2.21@45.085,52.705
UART4_RXD: P2.11 SOM1.B64 | length 48
  Top Layer w0.2: P2.11@32.385,52.705 31.191,51.511 31.191,48.412 31.739,47.864 31.739,46.9 32.881,45.758 32.881,45.3 37.008,41.173 v1@37.231,40.95 ; v1(56.363,37.44) 57.66,37.44 58.041,37.059 61.941,37.059 65.518,33.482 SOM1.B64@67.039,33.482
  Bottom Layer w0.2: v1(36.982,41.148) 37.752,41.148 38.1,40.8 38.7,40.8 39.1,40.4 53.402,40.4 v1(56.363,37.44)
UART4_TXD: P2.13 SOM1.B62 | length 48
  Top Layer w0.2: P2.13@34.925,52.705 33.5,51.28 33.5,46.72 38.8,41.42 v1(38.8,39.4) ; v1@55.606,36.652 61.748,36.652 65.418,32.982 SOM1.B62@67.039,32.982
  Bottom Layer w0.2: v1(38.8,39.4) 39.4,40 53.237,40 55.524,37.712 v1(55.524,36.703)
USB0_D_N: P5.2 SOM1.A63 | length 71.4
  Top Layer w0.254: P5.2@7.469,9.381 6.155,9.381 5.94,9.166 4.765,9.166 3.229,7.63 3.229,5.908 4.079,5.058 11.897,5.058 15.8,8.96 15.8,17.018 10.3,22.518 10.3,25.3 15.508,30.508 15.508,35.79 18.81,39.092 25.108,39.092 27.692,36.508 27.692,34.092 27.082,33.482 SOM1.A63@26.039,33.482
USB0_D_P: P5.3 SOM1.A61 | length 71.6
  Top Layer w0.254: P5.3@7.469,8.581 6.024,8.581 5.893,8.712 4.953,8.712 3.683,7.442 3.683,6.096 4.267,5.512 11.709,5.512 15.342,9.144 15.342,16.758 9.792,22.308 9.792,25.51 15,30.718 15,36 18.6,39.6 25.318,39.6 28.146,36.772 28.146,33.822 27.298,32.974 SOM1.A61@26.039,32.974
USB0_ID: P5.4 SOM1.A57 | length 64.1
  Top Layer w0.2: P5.4@7.469,7.781 11.22,7.781 14.4,10.961 14.4,17 11.8,19.6 11.4,19.6 9.225,21.775 9.225,25.81 10.207,26.792 ; 9.807,26.393 10.207,26.792 ; SOM1.A57@26.039,31.982 27.782,31.982 ; 27.8,32 27.782,31.982 ; 10.207,26.792 14.2,30.785 14.2,36.5 18.1,40.4 25.6,40.4 28.8,37.2 28.8,32.41 28.372,31.982 27.782,31.982
USB0_VBUS: C4.1 C11.2 P5.1 SOM1.A53 U1.6 | length 70
  Top Layer w0.2: P5.1@7.469,10.181 12.106,10.181 C4.1@12.219,10.068 12.468,10.068 13.6,11.2 13.6,17.206 11.606,19.2 11.234,19.2 8.825,21.609 8.825,26.225 9.561,26.961 13.8,31.2 13.8,36.7 17.9,40.8 21.057,40.8 ; U1.6@19.945,45.827 20.899,45.827 21.209,45.517 21.209,42.113 C11.2@21.057,41.961 21.057,40.8 ; 25.849,40.786 25.849,40.716 ; SOM1.A53@26.039,30.982 27.938,30.982 29.2,32.244 29.2,37.366 25.849,40.716 ; 21.057,40.8 25.766,40.8 25.849,40.716
USB1_DRVVBUS: R10.2 SOM1.B63 U2.4 | length 17.2
  Top Layer w0.2: SOM1.B63@72.039,33.482 72.884,33.482 73.779,32.587 73.779,31.249 74.423,30.605 75.335,30.605 76.29,31.56 78.24,31.56 80.1,29.7 82.207,29.7 82.889,30.382 82.889,30.389 83.039,30.539 U2.4@83.039,31.757 83.839,31.757 R10.2@84.314,31.282
USB1_N: P7.2 SOM1.B69 | length 3.7
  Top Layer w0.254: SOM1.B69@72.039,34.982 72.629,34.982 73.004,35.357 74.6,35.357 74.879,35.636 P7.2@74.879,36.205
USB1_OCN: R15.1 SOM1.B58 U2.5 | length 35.9
  Top Layer w0.2: v1(62.6,34.6) 65.218,31.982 SOM1.B58@67.039,31.982
  Top Layer w0.4: U2.5@83.1,36.4 R15.1@84.289,36.4 ; v1(84,34.6) 84,36.018
  Bottom Layer w0.2: v1(62.6,34.6) 65.644,37.644 70.755,37.644 71,37.4 75.8,37.4 78.07,39.67 82.25,39.67 84,37.92 v1(84,34.6)
USB1_P: P7.3 SOM1.B67 | length 3.5
  Top Layer w0.254: SOM1.B67@72.039,34.482 72.771,34.482 73.192,34.903 74.546,34.903 74.879,34.57 P7.3@74.879,34.205
USB1_VBUS: C6.1 C8.2 P7.1 R20.1 SOM1.B61 U2.6 U2.7 U2.8 | length 39
  Top Layer w0.2: SOM1.B61@72.039,32.982 72.818,32.982 73.379,32.421 73.379,31.084 74.323,30.14 75.93,30.14 v1(76.44,30.65) ; v1(82.38,38.23) 82.389,38.221 U2.6@82.389,35.957
  Top Layer w0.4: C8.2@74.539,40.87 74.879,40.53 P7.1@74.879,38.705 76.23,38.705 78.978,35.957 U2.8@81.089,35.957 U2.7@81.739,35.957 U2.6@82.389,35.957
  Bottom Layer w0.2: v1(76.44,30.65) 82.38,36.59 v1(82.38,38.23)
  Bottom Layer w0.508: C6.1@66.414,39.182 66.514,39.082 R20.1@70.189,39.082 70.197,39.082 71.179,38.1 73.4,38.1 74.005,38.705 P7.1@74.879,38.705
USBV_EN: P3.3 U1.2 | length 7.2
  Top Layer w0.305: P3.3@8.303,49.099 10.87,49.099 13.493,46.477 U1.2@14.395,46.477
USR0: Q2.2 R21.2 SOM1.B57 | length 73.5
  Top Layer w0.2: v1(26.848,8.738) 26.072,9.514 26.072,12.262 28.41,14.6 v1(42.4,14.6) ; v1@69.9,33.3 71.218,31.982 SOM1.B57@72.039,31.982
  Bottom Layer w0.2: Q2.2@14.249,6.467 14.399,6.317 14.399,6.018 14.575,5.842 18.654,5.842 18.756,5.944 23.431,5.944 26.225,8.738 v1(26.848,8.738) ; v1(42.4,14.6) 44.699,14.6 57.199,27.1 60.743,27.1 67.243,33.6 v1(70,33.6)
USR1: Q2.5 R23.2 SOM1.B50 | length 64.5
  Top Layer w0.2: v1(26.772,11.049) 28.221,9.6 40.247,9.6 57.647,27 62.4,27 65.382,29.982 SOM1.B50@67.039,29.982
  Bottom Layer w0.2: Q2.5@14.249,8.367 14.249,8.966 14.962,9.679 17.519,9.679 20.372,12.532 23.282,12.532 24.32,11.494 26.327,11.494 v1(26.772,11.049)
USR2: Q1.5 R17.2 SOM1.B52 | length 62
  Top Layer w0.2: v1(28.169,11.43) 29.199,10.4 31.039,10.4 40.482,10.4 57.482,27.4 62.2,27.4 65.282,30.482 SOM1.B52@67.039,30.482
  Bottom Layer w0.2: Q1.5@15.57,11.293 15.57,11.592 15.896,11.918 19.004,11.918 20.144,13.057 22.976,13.057 R17.2@23.266,13.348 24.371,12.244 27.355,12.244 v1(28.169,11.43)
USR3: Q1.2 R14.2 SOM1.B54 | length 59.7
  Top Layer w0.2: v1(28.2,13.4) 42.916,13.4 57.316,27.8 62,27.8 65.182,30.982 SOM1.B54@67.039,30.982
  Bottom Layer w0.2: Q1.2@15.57,13.193 15.57,13.492 16.048,13.97 20.951,13.97 R14.2@21.114,13.807 21.405,14.098 27.502,14.098 v1(28.2,13.4)
pads on no net: DA1.2 J1.2 J1.6 P1.11 P1.12 P1.13 P1.14 P1.15 P1.16 P1.17 P1.19 P4.free P5.SYSPAD10 P5.SYSPAD11 P6.0 P6.7 S1.2 S1.3 S1.5 S2.5 S3.5 SOM1.A10 SOM1.A12 SOM1.A14 SOM1.A18 SOM1.A25 SOM1.A40 SOM1.A44 SOM1.A46 SOM1.A55 SOM1.B24 SOM1.B26 SOM1.B28 SOM1.B30 SOM1.B32 SOM1.B33 SOM1.B34 SOM1.B36 SOM1.B38 SOM1.B55 SOM1.B56 SOM1.B60 SOM1.B68 SOM1.B70 SOM1.DGND@23.539,15.732 SOM1.DGND@23.539,37.232 SOM1.DGND@69.539,15.732 SOM1.DGND@69.539,37.232 SOM1.NC

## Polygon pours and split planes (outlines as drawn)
DGND on Top Layer "Cover" (solid, remove dead copper, pour order 15): 85.6,54 85.6,0.8 84,0.8 0.8,0.8 0.8,9.2 0.8,54 2.4,54
EARTH on Top Layer "Cover" (solid, pour order 19): 82.559,50.603 82.982,50.178 82.982,50.013 79.341,46.35 79.129,46.35 79.072,46.35 78.62,46.804 82.415,50.622 82.559,50.622
EARTH on Top Layer "Cover" (solid, pour order 17): 78.86,46.64 78.856,46.644 ccw(c80.652,48.44) 80.652,45.9 82.848,45.9 cw(c82.848,43.36) 84.644,45.156 85.5,44.3 cw(c84.776,43.576) 85.8,43.576 85.8,12.28 cw(c81.02,12.28) 84.4,8.9 cw(c84.159,9.141) 84.159,8.8 79.9,8.8 ccw(c79.9,7.593) 79.046,8.446 78.5,7.9 ccw(c79.466,6.934) 78.1,6.934 78.1,3.231 cw(c75.369,3.231) 77.3,1.3 77.136,1.136 cw(c75.6,2.673) 75.6,0.5 18.707,0.5 cw(c18.707,2.207) 17.5,1 cw(c18.224,1.724) 17.2,1.724 17.2,3.6 ccw(c15.269,3.6) 16.634,4.966 16,5.6 ccw(c15.517,5.117) 15.517,5.8 14.107,5.8 ccw(c14.107,4.093) 12.9,5.3 12.595,4.995 ccw(c13.79,3.8) 12.1,3.8 12.1,2.9 2.724,2.9 cw(c2.724,3.924) 2,3.2 1.873,3.327 cw(c4.946,6.4) 0.6,6.4 0.6,48.579 cw(c5.721,48.579) 2.1,52.2 cw(c6.204,48.096) 6.204,53.9 10.634,53.9 cw(c10.634,52.534) 11.6,53.5 cw(c11.359,53.259) 11.7,53.259 11.7,51.1 ccw(c14.114,51.1) 12.407,49.393 12.8,49 ccw(c14.007,50.207) 14.007,48.5 15.1,48.5 ccw(c15.1,50.431) 16.466,49.066 16.8,49.4 ccw(c15.351,50.849) 17.4,50.849 17.4,52.876 cw(c18.424,52.876) 17.7,53.6 cw(c18.666,52.634) 18.666,54 75.827,54 cw(c75.827,50.927) 78,53.1 cw(c77.276,52.376) 78.3,52.376 78.3,47.949 ccw(c80.349,47.949) 78.9,46.5 82.659,50.259 cw(c83,49.917) 83,50.4 83.07,50.43 82.506,50.994 ccw(c73.8,42.288) 73.8,54.6 6,54.6 ccw(c6,49.047) 2.074,52.974 1.768,52.668 ccw(c6.036,48.4) 0,48.4 0,6.67 ccw(c7.17,6.67) 2.1,1.6 ccw(c5.963,5.463) 5.963,0 73.809,0 ccw(c73.809,12.291) 82.5,3.6 82.835,3.935 ccw(c74.47,12.3) 86.3,12.3 86.3,42.533 ccw(c75.033,42.533) 83,50.5
EARTH on Top Layer "Cover" (solid, pour order 14): 12.192,33.807 12.192,34.62 0.3,34.6 0.3,12.4 9.8,12.4 12.9,15.5 12.9,17.7 12.5,18.1 12.116,18.72 11.201,18.872 9.728,18.339 8.458,17.272 6.045,17.247 2.896,17.247 2.9,21.3 2.9,26.2 2.921,32.182 7.747,32.207 10.414,32.106 12.116,32.106 12.167,32.918
EARTH on Bottom Layer "Cover" (solid, pour order 21): 83.083,50.137 82.798,50.414 82.798,50.419 82.486,50.419 78.686,46.731 78.969,46.456 79.058,46.456 79.292,46.456 83.083,50.137
EARTH on Bottom Layer "Cover" (solid, pour order 20): 78.86,46.64 78.856,46.644 ccw(c80.652,48.44) 80.652,45.9 82.848,45.9 cw(c82.848,43.36) 84.644,45.156 85.5,44.3 cw(c84.776,43.576) 85.8,43.576 85.8,12.28 cw(c81.02,12.28) 84.4,8.9 cw(c84.159,9.141) 84.159,8.8 79.9,8.8 ccw(c79.9,7.593) 79.046,8.446 78.5,7.9 ccw(c79.466,6.934) 78.1,6.934 78.1,3.231 cw(c75.369,3.231) 77.3,1.3 77.136,1.136 cw(c75.6,2.673) 75.6,0.5 18.707,0.5 cw(c18.707,2.207) 17.5,1 cw(c18.224,1.724) 17.2,1.724 17.2,3.6 ccw(c15.269,3.6) 16.634,4.966 16,5.6 ccw(c15.517,5.117) 15.517,5.8 14.107,5.8 ccw(c14.107,4.093) 12.9,5.3 12.595,4.995 ccw(c13.79,3.8) 12.1,3.8 12.1,2.34 2.724,2.34 2.724,2.9 cw(c2.724,3.924) 2,3.2 1.873,3.327 cw(c4.946,6.4) 0.6,6.4 0.6,48.579 cw(c5.721,48.579) 2.1,52.2 cw(c6.204,48.096) 6.204,53.9 10.634,53.9 cw(c10.634,52.534) 11.6,53.5 cw(c11.359,53.259) 11.7,53.259 11.7,51.1 ccw(c14.114,51.1) 12.407,49.393 12.8,49 ccw(c14.007,50.207) 14.007,48.5 15.1,48.5 ccw(c15.1,50.431) 16.466,49.066 16.8,49.4 ccw(c15.351,50.849) 17.4,50.849 17.4,52.876 cw(c18.424,52.876) 17.7,53.6 cw(c18.666,52.634) 18.666,54 75.827,54 cw(c75.827,50.927) 78,53.1 cw(c77.276,52.376) 78.3,52.376 78.3,47.949 ccw(c80.349,47.949) 78.9,46.5 82.659,50.259 cw(c83,49.917) 83,50.4 83.07,50.43 82.506,50.994 ccw(c73.8,42.288) 73.8,54.6 6,54.6 ccw(c6,49.047) 2.074,52.974 1.768,52.668 ccw(c6.036,48.4) 0,48.4 0,6.67 ccw(c7.17,6.67) 2.1,1.6 ccw(c5.963,5.463) 5.963,0 73.809,0 ccw(c73.809,12.291) 82.5,3.6 82.835,3.935 ccw(c74.47,12.3) 86.3,12.3 86.3,42.533 ccw(c75.033,42.533) 83,50.5
DGND on Bottom Layer "Cover" (solid, remove dead copper, pour order 16): 85.6,54 85.6,0.8 0.8,0.8 0.8,6.4 0.8,54

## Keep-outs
Keep-Out Layer:
  lines w0.254: -0.152,6.378 -0.152,48.412 cw(c6.312,48.273) 6.452,54.737 73.693,54.762 ; -0.151,6.222 ccw(c6.378,6.378) 6.533,-0.151 ; 6.378,-0.152 73.528,-0.152 ccw(c73.688,12.647) 86.487,12.487 86.487,41.974 ; 73.781,54.762 cw(c73.698,41.974) 86.487,41.891

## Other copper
Top Layer:
  rectangle net SYS_5V: 30.8,41.6 32.5,43.7
  pour cut-out: 71.7,23.482 71.7,17.8 70.186,17.8 67.4,20.586 67.4,22.9 67.7,22.9 68.4,23.6
  pour cut-out: 77.089,1.727 77.038,2.159 75.6,6.6 71.239,10.961 71.239,16.181 67.938,19.482 67.156,18.7 66.2,18.7 66.2,16.2 69.4,13 69.4,1.2 69.73,0.87 75.591,0.87 76.977,1.256
  pour cut-out: 3.429,51.741 cw(c3.429,50.241) 4.929,50.241 cw(c3.429,50.241) 3.429,48.741 cw(c3.429,50.241) 1.929,50.241 cw(c3.429,50.241) 3.429,51.741
  pour cut-out: 75.87,47.957 cw(c75.87,46.457) 77.37,46.457 cw(c75.87,46.457) 75.87,44.957 cw(c75.87,46.457) 74.37,46.457 cw(c75.87,46.457) 75.87,47.957
  pour cut-out: 19.888,15.165 cw(c19.888,13.665) 21.388,13.665 cw(c19.888,13.665) 19.888,12.165 cw(c19.888,13.665) 18.388,13.665 cw(c19.888,13.665) 19.888,15.165
Bottom Layer:
  rectangle net SYS_5V: 30.8,41.9 32.5,43.5
  pour cut-out: 76.251,46.788 ccw(c76.251,45.288) 74.751,45.288 ccw(c76.251,45.288) 76.251,43.788 ccw(c76.251,45.288) 77.751,45.288 ccw(c76.251,45.288) 76.251,46.788
  pour cut-out: 36.119,11.508 ccw(c36.119,10.008) 34.619,10.008 ccw(c36.119,10.008) 36.119,8.508 ccw(c36.119,10.008) 37.619,10.008 ccw(c36.119,10.008) 36.119,11.508
  pour cut-out: 2.642,39.219 ccw(c2.642,37.719) 1.142,37.719 ccw(c2.642,37.719) 2.642,36.219 ccw(c2.642,37.719) 4.142,37.719 ccw(c2.642,37.719) 2.642,39.219

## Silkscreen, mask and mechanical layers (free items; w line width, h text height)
Top Overlay:
  lines w0.254: 27.584,51.41 28.829,50.165 28.829,49.479 ; 78.943,21.844 80.061,21.844 ; 78.969,22.454 80.086,22.454 ; 78.969,23.063 80.086,23.063 ; 78.969,23.673 80.086,23.673 ; 78.537,21.539 78.537,24.079 78.613,24.155 83.287,24.155 83.287,20.676 83.134,20.523 81.051,20.523 80.366,21.209 78.867,21.209 78.537,21.539
  text "1" at 17.325,52.05 h1.52
  text "PWR button" at 4.801,41.554 h2 r270
  text "Reset" at 14.503,40.742 h1.52 r270
  text "1" at 79.223,40.259 h7
  text "MicroSD card" at 85.404,11.123 h2.5 r90
  text "uSomIQ System on Module" at 26.467,10.795 h4
  text "BootSelect" at 77.394,9.55 h1.52 r90
  text "1" at 17.325,3.625 h1.52
Bottom Overlay:
  rectangle: 30.302,36.728 58.141,41.783
  text "PWR" at 8.814,52.553 h1.52
  text "uSomIQ Bone Cape v3b" at 65.456,45.491 h5
  text "MENTOREL.ru" at 58.064,42.113 h5
  text "5VDC" at 13.487,39.954 h3.5 r270
  text "1" at 29.159,36.601 h10
  text "BAT_TS" at 24.536,25.273 h1.52
  text "BAT_SEN" at 24.511,23.597 h1.52
  text "BAT_IN" at 24.511,21.971 h1.52
  text "1" at 33.6,20.5 h1.52
  text "TX" at 46.304,19.685 h1.52 r90
  text "RX" at 43.866,19.583 h1.52 r90
  text "3.3" at 41.377,19.558 h1.52 r90
  text "GND" at 36.322,19.456 h1.52 r90
  text "UART0" at 45.491,15.824 h1.52
Mechanical 1:
  lines w0.254: 0,6.35 ccw(c6.35,6.35) 6.35,0 73.66,0 ccw(c73.66,12.7) 86.36,12.7 86.36,40.64 86.36,41.91 ccw(c73.66,41.91) 73.66,54.61 6.35,54.61 ccw(c6.35,48.26) 0,48.26 0,46.99 0,6.35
